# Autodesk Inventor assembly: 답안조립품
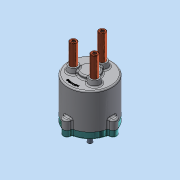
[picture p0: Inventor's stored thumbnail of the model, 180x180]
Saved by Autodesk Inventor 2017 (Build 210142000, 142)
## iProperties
Part Number: 답안조립품
Material: 일반
Document SubType Name: Assembly
Designer: MRC
Author: MRC
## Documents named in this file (14)
- C:\Users\MRC\Desktop\610708V1006\답안조립품.iam
- C:\Users\MRC\Desktop\610708V1006\본체.ipt
- C:\Users\MRC\Desktop\610708V1006\가변스프링1.ipt
- C:\Users\MRC\Desktop\610708V1006\가변스프링2.ipt
- C:\Users\MRC\Desktop\610708V1006\가변스프링3.ipt
- C:\Users\MRC\Desktop\610708V1006\멈춤링 10 x 1.ipt
- C:\Users\MRC\Desktop\610708V1006\멈춤링 22 x 1.2.ipt
- C:\Users\MRC\Desktop\610708V1006\메인 축.ipt
- C:\Users\MRC\Desktop\610708V1006\베어링 NA 4900.ipt
- C:\Users\MRC\Desktop\610708V1006\볼트 M5.ipt
- C:\Users\MRC\Desktop\610708V1006\슬라이드 축.ipt
- C:\Users\MRC\Desktop\610708V1006\오일실.ipt
- C:\Users\MRC\Desktop\610708V1006\커버.ipt
- C:\Users\MRC\Desktop\610708V1006\판캠.ipt
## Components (3 placed, 3 different names)
1. 가변스프링1:1
2. 가변스프링2:1
3. 가변스프링3:1
